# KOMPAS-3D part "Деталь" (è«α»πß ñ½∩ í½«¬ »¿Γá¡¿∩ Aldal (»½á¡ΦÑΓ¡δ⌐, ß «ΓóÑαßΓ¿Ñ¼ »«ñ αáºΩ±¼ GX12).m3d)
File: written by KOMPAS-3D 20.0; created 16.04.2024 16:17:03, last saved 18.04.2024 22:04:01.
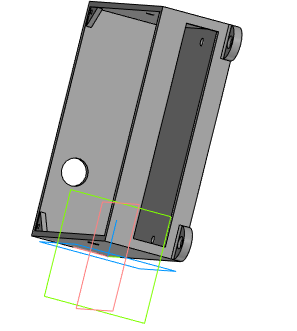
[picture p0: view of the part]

Document properties: Полное имя файла: D:\Soft 4 pads\Чертежи корпусов и т.д\Корпус для блок питания Aldal (планшетный, с отверстием под разъём GX12-2).m3d

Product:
- Part/product: Деталь
    Масса: 0.517868
  - Body: Тело 1
      Масса: 0.517663

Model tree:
1. Эскиз:1
2. Элемент выдавливания:1
     Расстояние 1 = 38
3. Эскиз:2  (with: Элемент выдавливания:1)
4. Элемент выдавливания:2
     Расстояние 2 = 35
5. Эскиз:3  (with: Элемент выдавливания:1)
6. Элемент выдавливания:3
     Расстояние 2 = 4
7. Скругление:1  (with: Элемент выдавливания:3)
     Радиус = 1
8. Скругление:2  (with: Элемент выдавливания:3)
     Радиус = 1
9. Скругление:3  (with: Элемент выдавливания:3)
     Радиус = 1
10. Скругление:4  (with: Элемент выдавливания:3)
     Радиус = 1
11. Эскиз:4  (with: Элемент выдавливания:1, Элемент выдавливания:3)
12. Элемент выдавливания:4
     Расстояние 2 = 10
13. Скругление:5  (with: Элемент выдавливания:4)
     Радиус = 1
14. Скругление:6  (with: Элемент выдавливания:4)
     Радиус = 1
15. Скругление:7  (with: Элемент выдавливания:4)
     Радиус = 1
16. Скругление:8  (with: Элемент выдавливания:4)
     Радиус = 1
17. Эскиз:5  (with: Элемент выдавливания:2)
18. Элемент выдавливания:5
     Расстояние 2 = 10
19. Скругление:9  (with: Элемент выдавливания:5)
     Радиус = 1
20. Скругление:10  (with: Элемент выдавливания:5)
     Радиус = 1
21. Скругление:11  (with: Элемент выдавливания:5)
     Радиус = 1
22. Скругление:12  (with: Элемент выдавливания:5)
     Радиус = 1
23. Эскиз:6  (with: Элемент выдавливания:2)
24. Элемент выдавливания:6
     Расстояние 2 = 10
25. Эскиз:7  (with: Элемент выдавливания:1)
26. Элемент выдавливания:7
     Расстояние 2 = 10
27. Эскиз:8  (with: Элемент выдавливания:1, Элемент выдавливания:2)
28. Элемент выдавливания:8
     Расстояние 2 = 3
29. Эскиз:9  (with: Элемент выдавливания:1, Элемент выдавливания:2)
30. Элемент выдавливания:9
     Расстояние 2 = 0.5
31. Эскиз:10  (with: Элемент выдавливания:9)
32. Элемент выдавливания:10
     Расстояние 2 = 10
33. Эскиз:11  (with: Элемент выдавливания:9)
34. Элемент выдавливания:11
     Расстояние 2 = 10
35. Эскиз:12  (with: Элемент выдавливания:9)
36. Элемент выдавливания:12
     Расстояние 2 = 10
37. Эскиз:13  (with: Элемент выдавливания:9)
38. Элемент выдавливания:13
     Расстояние 2 = 10
39. Эскиз:14  (with: Элемент выдавливания:2)
40. Элемент выдавливания:14
     Расстояние 1 = 110; Расстояние 2 = 5
41. Скругление:21  (with: Элемент выдавливания:14)
     Радиус = 1
42. Скругление:22  (with: Элемент выдавливания:14)
     Радиус = 1
43. Эскиз:15  (with: Элемент выдавливания:2, Элемент выдавливания:14)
